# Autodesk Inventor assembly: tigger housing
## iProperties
Created: 2006-04
Part Number: tigger housing
Checked By: Оголихин
Description: Наименование
Document SubType Name: Weldment
Mfg Approved By: Малюсейко
Designer: Калинин
Engineer: Технолог
Manufacturer: Standard
Standards Organization: Custom
Author: Калинин
